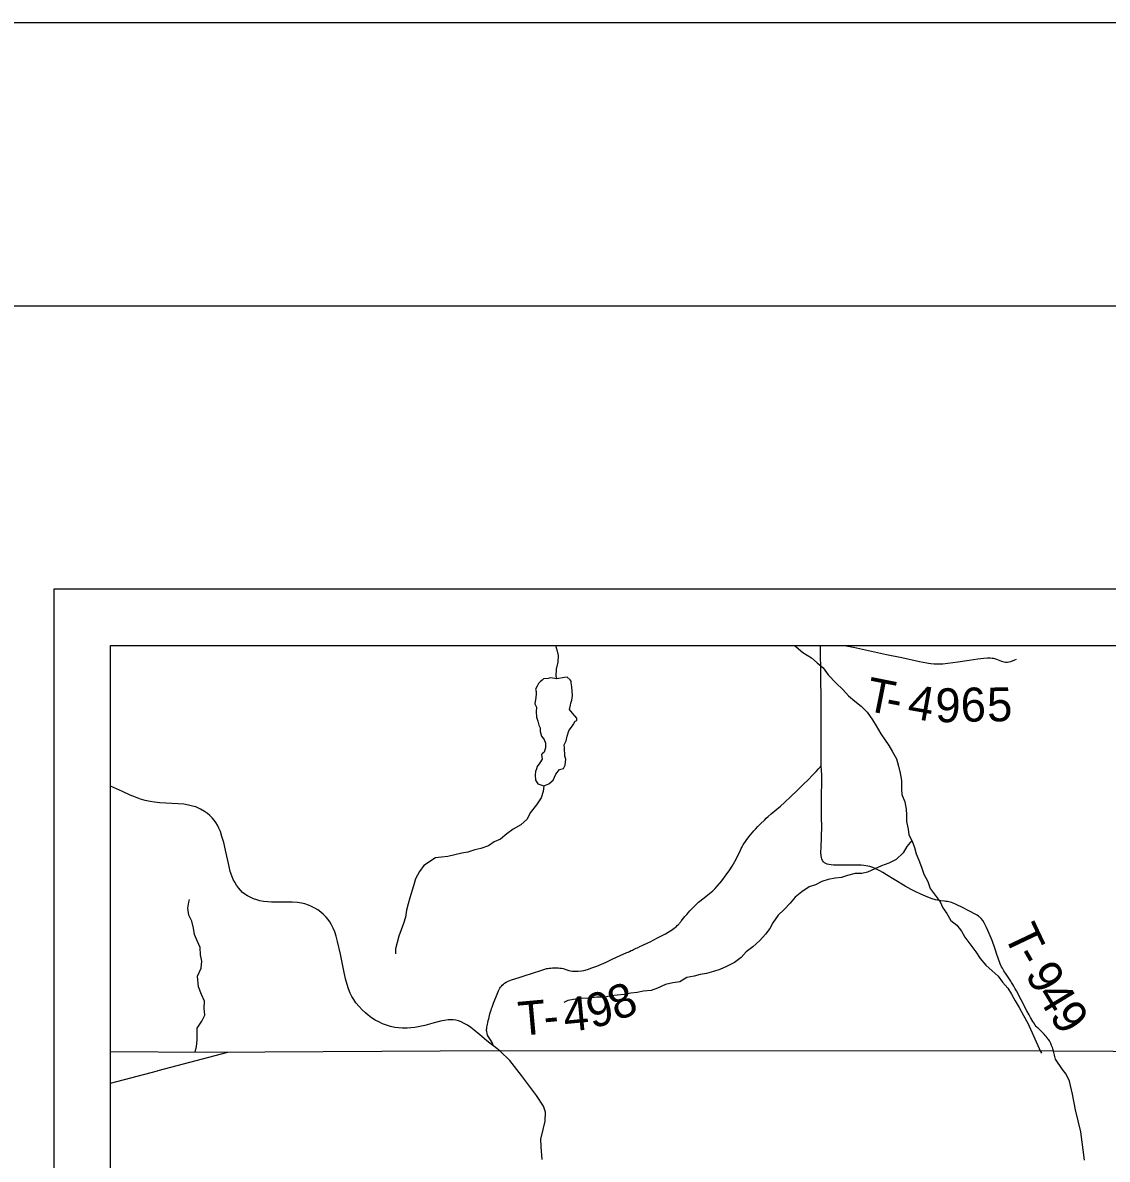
# Model space of a CAD drawing. Extents: x 0 to 2329303, y 0 to 694397.
# Drawn here: x 1.945 to 3.861, y 19.992 to 22 of the extents above; entities that cross this region are included whole.
import ezdxf

# ---------------------------------------------------------------- set-up
doc = ezdxf.new("R2010")
doc.units = 0
for name, color, linetype in [('GM_X_Minor_Lake', 7, 'Continuous'), ('GM_X_Minor_River', 7, 'Continuous'), ('GM_X_State_Route', 7, 'Continuous'), ('GM_X_Township', 7, 'Continuous'), ('GM_X_Township_Road', 7, 'Continuous'), ('GM_X_Township_Road_Text', 7, 'Continuous'), ('SH_Border', 7, 'Continuous'), ('SH_Cut_Line', 7, 'Continuous'), ('SH_Data', 7, 'Continuous')]:
    doc.layers.add(name, color=color, linetype=linetype)

msp = doc.modelspace()

# ---------------------------------------------------------------- linework, layer by layer
at = {"layer": 'GM_X_Minor_Lake'}
for points in [[(2.8883, 20.8412), (2.8771, 20.8429), (2.8731, 20.8416), (2.8651, 20.841), (2.8624, 20.8389), (2.8588, 20.836), (2.8561, 20.8327), (2.8539, 20.8278), (2.8508, 20.8229), (2.8517, 20.8189), (2.8518, 20.8145), (2.8512, 20.8081), (2.8499, 20.7968), (2.8525, 20.7909), (2.8519, 20.7825), (2.8525, 20.7733), (2.8547, 20.7665), (2.8569, 20.7594), (2.859, 20.7546), (2.8588, 20.7482), (2.8614, 20.7399), (2.866, 20.734), (2.8682, 20.7272), (2.8684, 20.7192), (2.8662, 20.7115), (2.8627, 20.7086), (2.8611, 20.7074), (2.8625, 20.699), (2.8583, 20.6929), (2.8537, 20.6863), (2.8526, 20.6823), (2.8507, 20.6774), (2.8501, 20.6714), (2.8507, 20.6618), (2.8549, 20.6555), (2.8654, 20.6522)], [(2.8654, 20.6522), (2.8745, 20.6557), (2.8823, 20.6623), (2.8868, 20.6725), (2.893, 20.6811), (2.9001, 20.6825), (2.9032, 20.6886), (2.9045, 20.699), (2.9027, 20.7046), (2.9019, 20.7198), (2.9014, 20.7246), (2.9052, 20.7315), (2.9066, 20.7396), (2.9099, 20.7493), (2.9122, 20.753), (2.9161, 20.7583), (2.918, 20.7607), (2.9211, 20.766), (2.9238, 20.7677), (2.9241, 20.7713), (2.9163, 20.7803), (2.9109, 20.7866), (2.9127, 20.7943), (2.9134, 20.7983), (2.9149, 20.8031), (2.9159, 20.8116), (2.9157, 20.8192), (2.915, 20.8272), (2.9137, 20.834), (2.9136, 20.8372), (2.9119, 20.8395), (2.9066, 20.8442), (2.9018, 20.8436), (2.8883, 20.8412)]]:
    msp.add_lwpolyline(points, dxfattribs=at)
at = {"layer": 'GM_X_Minor_River'}
for points in [[(2.8861, 20.9), (2.8885, 20.8925), (2.8908, 20.8822), (2.8903, 20.8706), (2.8874, 20.8584), (2.887, 20.8456), (2.8883, 20.8412)], [(3.307, 20.9), (3.3117, 20.8973), (3.3231, 20.8876), (3.3386, 20.8784), (3.3488, 20.8691), (3.3594, 20.8606), (3.3682, 20.848), (3.3818, 20.8332), (3.3936, 20.8223), (3.4039, 20.811), (3.415, 20.8017), (3.4264, 20.7928), (3.4371, 20.7823), (3.4463, 20.7685), (3.4525, 20.7583), (3.4613, 20.7437), (3.4754, 20.7233), (3.4817, 20.7123), (3.4885, 20.6996), (3.4924, 20.6869), (3.4951, 20.6746), (3.4975, 20.6614), (3.4975, 20.647), (3.4982, 20.6366), (3.5033, 20.6235), (3.5057, 20.6107), (3.5063, 20.6007), (3.5066, 20.5891), (3.5094, 20.5752), (3.5105, 20.5652), (3.5164, 20.5541), (3.5207, 20.543), (3.5234, 20.5319), (3.5281, 20.5208), (3.5328, 20.5085), (3.5371, 20.4958), (3.5439, 20.4828), (3.5482, 20.4709), (3.566, 20.4474), (3.5703, 20.4367), (3.5778, 20.4265), (3.5849, 20.4142), (3.5951, 20.4057), (3.6038, 20.3955), (3.6097, 20.3849), (3.6184, 20.3731), (3.6291, 20.359), (3.6366, 20.3472), (3.6466, 20.3355), (3.658, 20.3254), (3.6683, 20.3156), (3.6761, 20.3055), (3.6856, 20.2945), (3.6919, 20.2839), (3.6982, 20.2724), (3.7053, 20.2602), (3.7133, 20.2464), (3.7209, 20.2326), (3.743, 20.1829), (3.7447, 20.18)], [(2.8654, 20.6522), (2.8641, 20.6421), (2.8608, 20.6308), (2.8523, 20.6185), (2.8411, 20.6042), (2.8362, 20.5932), (2.8249, 20.5833), (2.8111, 20.5752), (2.8001, 20.5673), (2.7892, 20.5578), (2.7777, 20.553), (2.7675, 20.5459), (2.754, 20.5415), (2.7433, 20.5388), (2.7314, 20.5348), (2.7207, 20.5329), (2.7084, 20.5302), (2.6961, 20.527), (2.6845, 20.5262), (2.6741, 20.5247), (2.6537, 20.5113), (2.6456, 20.5007), (2.6388, 20.4876), (2.6351, 20.4751), (2.6285, 20.4541), (2.6256, 20.4435), (2.6231, 20.4322), (2.621, 20.4198), (2.6177, 20.4088), (2.6136, 20.3979), (2.6095, 20.3862), (2.6066, 20.3752), (2.6033, 20.3639), (2.6036, 20.3551)], [(3.5157, 20.5554), (3.507, 20.5446), (3.5005, 20.5336), (3.4884, 20.5221), (3.475, 20.5153), (3.4624, 20.5105), (3.4505, 20.5053), (3.4375, 20.4997), (3.4272, 20.4974), (3.4156, 20.4971), (3.4021, 20.4939), (3.3918, 20.49), (3.3802, 20.4892), (3.3679, 20.4865), (3.3568, 20.4829), (3.3453, 20.4774), (3.3343, 20.4735), (3.3213, 20.4647), (3.3096, 20.4551), (3.3007, 20.4448), (3.2902, 20.4333), (3.2796, 20.4234), (3.2704, 20.4103), (3.2647, 20.4001), (3.257, 20.3898), (3.2473, 20.3787), (3.2348, 20.3675), (3.223, 20.3588), (3.2141, 20.3485), (3.2023, 20.3397), (3.1885, 20.3329), (3.1767, 20.3278), (3.1652, 20.3238), (3.1529, 20.3203), (3.1418, 20.3187), (3.131, 20.316), (3.1183, 20.3132), (3.1061, 20.3061), (3.0934, 20.3041), (3.0807, 20.3009), (3.0661, 20.2949), (3.055, 20.2905), (3.0418, 20.2894), (3.0303, 20.287), (3.0195, 20.2859), (3.0072, 20.2835), (2.9953, 20.282), (2.9837, 20.2812), (2.9733, 20.2789), (2.959, 20.2785), (2.947, 20.277), (2.9318, 20.2765), (2.9215, 20.275), (2.908, 20.2726), (2.9009, 20.2692)], [(2.2495, 20.1814), (2.2515, 20.1918), (2.253, 20.2026), (2.2532, 20.2133), (2.2529, 20.2242), (2.2614, 20.2364), (2.2663, 20.247), (2.2652, 20.2594), (2.2656, 20.2718), (2.2605, 20.2833), (2.2554, 20.2972), (2.2533, 20.316), (2.2601, 20.3298), (2.2609, 20.3423), (2.259, 20.3534), (2.2583, 20.3662), (2.2536, 20.3773), (2.2481, 20.3896), (2.2466, 20.4008), (2.2435, 20.4127), (2.238, 20.4238), (2.2364, 20.4361), (2.2381, 20.4466), (2.2392, 20.4515)]]:
    msp.add_lwpolyline(points, dxfattribs=at)
at = {"layer": 'GM_X_State_Route'}
for points in [[(2.7886, 20.1833), (2.7825, 20.1882), (2.7772, 20.1921), (2.7756, 20.1932), (2.7648, 20.2018), (2.7522, 20.2124), (2.7427, 20.2204), (2.7365, 20.2251), (2.7305, 20.2291), (2.7249, 20.2324), (2.7197, 20.2349), (2.7149, 20.2367), (2.7099, 20.2379), (2.7055, 20.2385), (2.7016, 20.2387), (2.6965, 20.2385), (2.6901, 20.2376), (2.683, 20.2362), (2.6717, 20.2332), (2.6552, 20.2287), (2.6462, 20.2267), (2.6377, 20.2252), (2.6305, 20.2244), (2.6239, 20.224), (2.616, 20.224), (2.6087, 20.2246), (2.6022, 20.2254), (2.5944, 20.2271), (2.5875, 20.2293), (2.5807, 20.2318), (2.5741, 20.2349), (2.5677, 20.2383), (2.561, 20.2425), (2.5551, 20.2468), (2.5501, 20.251), (2.5443, 20.2565), (2.539, 20.2623), (2.5336, 20.269), (2.5298, 20.2744), (2.5264, 20.2801), (2.5234, 20.286), (2.5204, 20.2933), (2.5179, 20.3009), (2.5153, 20.3111), (2.5115, 20.3284), (2.5061, 20.3547), (2.5011, 20.3771), (2.4986, 20.3866), (2.4962, 20.394), (2.4934, 20.4006), (2.4906, 20.4064), (2.4873, 20.412), (2.4843, 20.4162), (2.481, 20.4202), (2.4764, 20.4248), (2.4715, 20.4289), (2.4662, 20.4327), (2.4607, 20.4361), (2.4549, 20.4391), (2.4496, 20.4414), (2.4434, 20.4435), (2.4371, 20.445), (2.4301, 20.4459), (2.421, 20.4465), (2.4033, 20.4467), (2.3843, 20.4467), (2.3777, 20.447), (2.3704, 20.4477), (2.3639, 20.449), (2.3581, 20.4505), (2.3525, 20.4524), (2.3464, 20.4551), (2.3418, 20.4577), (2.3373, 20.4605), (2.3331, 20.4639), (2.3293, 20.4676), (2.3258, 20.4716), (2.3223, 20.4764), (2.3192, 20.4816), (2.3168, 20.4863), (2.3139, 20.493), (2.3115, 20.5006), (2.3092, 20.5095), (2.303, 20.5384), (2.2998, 20.5518), (2.2967, 20.5625), (2.2939, 20.5711), (2.2915, 20.5772), (2.2889, 20.5823), (2.2858, 20.5873), (2.2828, 20.5915), (2.2795, 20.5954), (2.2754, 20.5995), (2.2709, 20.6032), (2.2656, 20.6069), (2.2589, 20.6109), (2.2544, 20.6132), (2.2503, 20.6148), (2.2447, 20.6164), (2.2378, 20.618), (2.2295, 20.6194), (2.2192, 20.6203), (2.2081, 20.621), (2.1872, 20.6222), (2.1774, 20.6232), (2.1696, 20.6243), (2.1612, 20.6261), (2.153, 20.6284), (2.1437, 20.6318), (2.1346, 20.6356), (2.1209, 20.6418), (2.1, 20.6517)], [(2.8627, 19.9922), (2.8606, 20.0144), (2.8605, 20.0279), (2.8641, 20.0452), (2.8677, 20.0597), (2.8686, 20.0758), (2.8651, 20.0863), (2.8525, 20.1051), (2.8261, 20.1402), (2.8057, 20.1668), (2.7886, 20.1833)]]:
    msp.add_lwpolyline(points, dxfattribs=at)
at = {"layer": 'GM_X_Township'}
msp.add_lwpolyline([(5.5032, 20.182), (5.102, 20.1805), (5.0168, 20.1816), (4.9486, 20.1829), (4.6141, 20.1787), (3.7653, 20.1833), (2.7861, 20.1837), (2.2689, 20.1812), (2.1, 20.1819)], dxfattribs=at)
at = {"layer": 'GM_X_Township_Road'}
for points in [[(3.3558, 20.6871), (3.3554, 20.6997), (3.3554, 20.7194), (3.3553, 20.7305), (3.3555, 20.7436), (3.3556, 20.7587), (3.3555, 20.7646), (3.3555, 20.7797), (3.3555, 20.7889), (3.3554, 20.7974), (3.3554, 20.8026), (3.3554, 20.8123), (3.3554, 20.8155), (3.3553, 20.8195), (3.3551, 20.8295), (3.3551, 20.8361), (3.3547, 20.8465), (3.3548, 20.8557), (3.3548, 20.8655), (3.3544, 20.8773), (3.3543, 20.8832), (3.3544, 20.8983), (3.3544, 20.9)], [(3.3962, 20.9), (3.3964, 20.9), (3.4125, 20.8968), (3.4709, 20.8841), (3.4979, 20.8785), (3.5293, 20.8716), (3.536, 20.8703), (3.5422, 20.8691), (3.5454, 20.8685), (3.5493, 20.868), (3.5552, 20.8676), (3.5624, 20.8674), (3.5703, 20.8677), (3.5795, 20.8685), (3.597, 20.8708), (3.6171, 20.8739), (3.6327, 20.8764), (3.643, 20.8778), (3.6496, 20.8782), (3.6541, 20.8782), (3.658, 20.8777), (3.66, 20.8774), (3.6619, 20.8769), (3.6656, 20.8757), (3.6742, 20.8723), (3.6786, 20.8711), (3.6812, 20.8706), (3.6844, 20.8706), (3.687, 20.8709), (3.6908, 20.8719), (3.6976, 20.8744), (3.7006, 20.8758)], [(2.7772, 20.1921), (2.775, 20.1968), (2.774, 20.1988), (2.7723, 20.2017), (2.7703, 20.2049), (2.7677, 20.2087), (2.7662, 20.2116), (2.7651, 20.2146), (2.7645, 20.2178), (2.7643, 20.2196), (2.7643, 20.2217), (2.7645, 20.2236), (2.7647, 20.2257), (2.7651, 20.2282), (2.7657, 20.2308), (2.7663, 20.2331), (2.7673, 20.2374), (2.7681, 20.2406), (2.7688, 20.2432), (2.7696, 20.2463), (2.7703, 20.2491), (2.7714, 20.2527), (2.7723, 20.2556), (2.7732, 20.2586), (2.774, 20.2611), (2.7753, 20.2647), (2.7767, 20.2684), (2.7788, 20.2739), (2.7806, 20.2781), (2.7818, 20.2811), (2.7829, 20.284), (2.7842, 20.2872), (2.7854, 20.2897), (2.7868, 20.2925), (2.788, 20.2944), (2.7892, 20.2964), (2.7905, 20.2982), (2.7921, 20.2999), (2.794, 20.3016), (2.796, 20.3033), (2.7988, 20.305), (2.8023, 20.3068), (2.8084, 20.3092), (2.8221, 20.3137), (2.8358, 20.3182), (2.8402, 20.3195), (2.8452, 20.321), (2.86, 20.3261), (2.867, 20.3282), (2.8704, 20.3291), (2.8726, 20.3294), (2.8747, 20.3298), (2.8778, 20.3301), (2.8808, 20.3303), (2.8841, 20.3305), (2.8884, 20.3305), (2.8909, 20.3304), (2.8936, 20.3302), (2.8965, 20.3298), (2.8996, 20.3291), (2.9016, 20.3285), (2.9043, 20.3277), (2.9098, 20.3261), (2.9128, 20.3253), (2.9162, 20.3247), (2.9211, 20.3244), (2.9261, 20.3245), (2.9318, 20.325), (2.9362, 20.3259), (2.9425, 20.3276), (2.9506, 20.3303), (2.9592, 20.3336), (2.9754, 20.3408), (2.9861, 20.3457), (3.0004, 20.3522), (3.0122, 20.3574), (3.0145, 20.3585), (3.0169, 20.3596), (3.0198, 20.3609), (3.0222, 20.362), (3.024, 20.3629), (3.0263, 20.3639), (3.0287, 20.365), (3.0311, 20.3661), (3.0352, 20.368), (3.0404, 20.3705), (3.0491, 20.3747), (3.0543, 20.3771), (3.0587, 20.3794), (3.0675, 20.384), (3.0723, 20.3864), (3.0757, 20.3881), (3.0804, 20.3907), (3.0852, 20.3936), (3.0909, 20.3971), (3.0959, 20.4006), (3.0992, 20.4032), (3.1019, 20.4058), (3.1035, 20.4073), (3.1044, 20.4084), (3.1052, 20.4094), (3.1059, 20.4103), (3.1069, 20.4115), (3.1077, 20.4126), (3.1085, 20.4137), (3.1097, 20.4152), (3.1123, 20.4185), (3.1148, 20.4214), (3.1165, 20.423), (3.118, 20.4249), (3.1206, 20.4278), (3.1238, 20.431), (3.1273, 20.4349), (3.1328, 20.4404), (3.1361, 20.4437), (3.1391, 20.4463), (3.1486, 20.4541), (3.1553, 20.4595), (3.1639, 20.4665), (3.1682, 20.4705), (3.1726, 20.4754), (3.1801, 20.4845), (3.188, 20.4949), (3.1941, 20.5035), (3.1983, 20.5101), (3.2031, 20.5186), (3.2116, 20.5355), (3.2144, 20.5415), (3.2158, 20.5444), (3.2178, 20.5478), (3.2228, 20.5554), (3.2279, 20.5621), (3.2368, 20.5725), (3.2393, 20.5755), (3.2437, 20.5803), (3.2478, 20.5845), (3.2558, 20.592), (3.2586, 20.5947), (3.262, 20.5976), (3.2675, 20.6023), (3.2739, 20.6077), (3.2838, 20.6163), (3.2905, 20.6224), (3.3018, 20.6331), (3.3126, 20.6434), (3.3187, 20.6491), (3.3252, 20.6554), (3.3322, 20.6623), (3.3408, 20.6712), (3.3466, 20.6774), (3.351, 20.6821), (3.3558, 20.6871)], [(3.7663, 20.1831), (3.7649, 20.1877), (3.7641, 20.1901), (3.7627, 20.1935), (3.7613, 20.1966), (3.759, 20.2013), (3.7579, 20.2031), (3.7569, 20.2047), (3.7552, 20.207), (3.7533, 20.2094), (3.7516, 20.2113), (3.7498, 20.2133), (3.7442, 20.2188), (3.739, 20.2239), (3.7375, 20.2254), (3.7357, 20.2272), (3.7338, 20.2295), (3.7312, 20.2332), (3.7295, 20.2359), (3.7256, 20.2427), (3.7243, 20.245), (3.7232, 20.2473), (3.7192, 20.2547), (3.7091, 20.2738), (3.7005, 20.29), (3.698, 20.2945), (3.6959, 20.2984), (3.6943, 20.3012), (3.692, 20.3049), (3.6907, 20.3071), (3.6874, 20.3124), (3.6827, 20.3191), (3.6785, 20.3252), (3.676, 20.3298), (3.6745, 20.3326), (3.6721, 20.3378), (3.6654, 20.3559), (3.664, 20.36), (3.6606, 20.3704), (3.6595, 20.3735), (3.6575, 20.3789), (3.6527, 20.3911), (3.6479, 20.4019), (3.6435, 20.41), (3.6411, 20.4139), (3.6383, 20.4175), (3.6373, 20.4187), (3.636, 20.4199), (3.6348, 20.4209), (3.6335, 20.4219), (3.6314, 20.4233), (3.6291, 20.4247), (3.6163, 20.4315), (3.6053, 20.4372), (3.594, 20.4426), (3.5886, 20.4449), (3.5858, 20.4458), (3.5836, 20.4465), (3.5814, 20.4471), (3.5791, 20.4475), (3.5761, 20.448), (3.5733, 20.4484), (3.5668, 20.449), (3.561, 20.4499), (3.5578, 20.4506), (3.5515, 20.4525), (3.5442, 20.4553), (3.5315, 20.4607), (3.5214, 20.4654), (3.5144, 20.4691), (3.5041, 20.4749), (3.4845, 20.4868), (3.4711, 20.495), (3.4644, 20.4991), (3.4592, 20.502), (3.4522, 20.5055), (3.4467, 20.5077), (3.4418, 20.5093), (3.4382, 20.5102), (3.4347, 20.5109), (3.4308, 20.5115), (3.4263, 20.5117), (3.4151, 20.5118), (3.4014, 20.5118), (3.3856, 20.5118), (3.3804, 20.5119), (3.3771, 20.512), (3.3732, 20.5122), (3.3693, 20.5128), (3.3661, 20.5137), (3.3637, 20.5147), (3.3616, 20.5162), (3.3597, 20.518), (3.3582, 20.5201), (3.3568, 20.523), (3.356, 20.5255), (3.3555, 20.5281), (3.3553, 20.53), (3.3552, 20.532), (3.3552, 20.5352), (3.3555, 20.5424), (3.3556, 20.5463), (3.3558, 20.5496), (3.3561, 20.5548), (3.3563, 20.562), (3.3565, 20.5804), (3.3564, 20.5961), (3.3562, 20.6138), (3.3561, 20.6362), (3.3567, 20.6571), (3.3567, 20.6715), (3.3563, 20.6794), (3.3558, 20.6871)], [(2.1842, 20.1491), (2.3069, 20.1814)], [(3.8211, 19.9908), (3.8144, 20.041), (3.805, 20.08), (3.7996, 20.1076), (3.7943, 20.1305), (3.7884, 20.1426), (3.7823, 20.1507), (3.7698, 20.169), (3.7663, 20.1831)], [(2.1, 20.1269), (2.183, 20.1488), (2.1842, 20.1491)]]:
    msp.add_lwpolyline(points, dxfattribs=at)
at = {"layer": 'SH_Border'}
msp.add_lwpolyline([(1.5, 21.5), (33.5, 21.5), (33.5, 0.5), (1.5, 0.5)], close=True, dxfattribs=at)
at = {"layer": 'SH_Cut_Line'}
msp.add_lwpolyline([(0, 0), (34, 0), (34, 22), (0, 22)], close=True, dxfattribs=at)
at = {"layer": 'SH_Data'}
for points in [[(2, 21), (9, 21), (9, 14), (2, 14)], [(2.1, 20.9), (8.9, 20.9), (8.9, 14.1), (2.1, 14.1)]]:
    msp.add_lwpolyline(points, close=True, dxfattribs=at)

# ---------------------------------------------------------------- texts
at = {"layer": 'GM_X_Township_Road_Text'}
for s, rotation, p in [('T', 348.7794, (3.4312, 20.7857)), ('4', 349.9991, (3.5058, 20.773)), ('9', 359.3427, (3.557, 20.7646)), ('6', 1.3067, (3.6027, 20.765)), ('5', 1.4287, (3.6494, 20.7654)), ('-', 348.9744, (3.4669, 20.7789)), ('T', 295.3291, (3.6773, 20.3904)), ('-', 300.0071, (3.6949, 20.3519)), ('9', 299.8913, (3.7149, 20.3194)), ('8', 23.3615, (2.9951, 20.2357)), ('4', 5.4519, (2.9028, 20.2175)), ('9', 15.0531, (2.9504, 20.223)), ('4', 301.4709, (3.7343, 20.2834)), ('T', 5.1495, (2.8228, 20.2104)), ('9', 304.6177, (3.7574, 20.2453)), ('-', 5.2067, (2.8675, 20.2144))]:
    msp.add_text(s, height=0.06, rotation=rotation, dxfattribs=at).set_placement(p)

doc.saveas('drawing.dxf')
